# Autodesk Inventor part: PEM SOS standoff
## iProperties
Author: John A. Hunter
Shininess: 64.0
Angle Display Precision: 2
Document Length Units: 11272
Document Angle Units: 11286
Document Time Units: 11279
Document Mass Units: 11290
Document Length Units Precision: 3
Document Angle Units Precision: 2
Compacted: True
PropertySet Name: _Private Model Information
Created: 2002-08
Part Number: PEM SOS standoff
Material: Stainless Steel, 440C
Description: SOS-632-6
Document SubType Name: Modeling
Designer: John A. Hunter
Control State: 0
Master: False
Checked Out: False
PropertySet Name: Design Tracking Control
Density: 0.0
Volumn: 0.0
Area: 0.0
PropertySet Name: Model Information
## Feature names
1. Extrusion1
2. Extrusion2
3. Hole1
